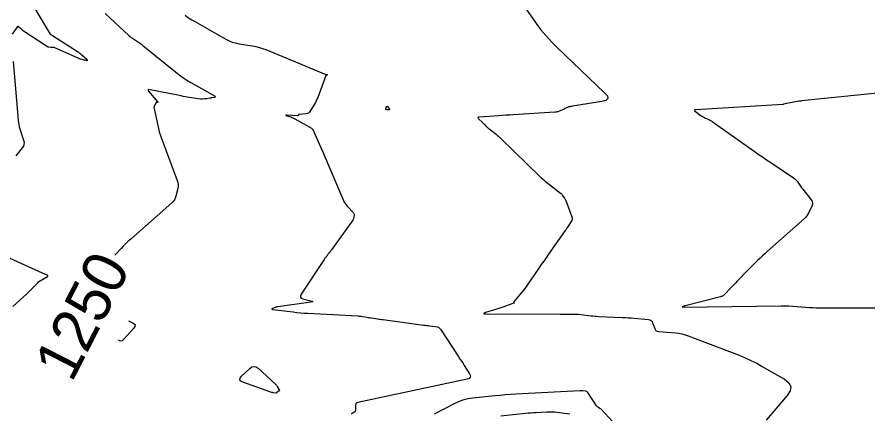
# Model space of a CAD drawing. Extents: x 658976 to 668726, y 639543 to 647196.
# Drawn here: x 662130.9 to 662247.5, y 641700.5 to 641754.9 of the extents above; entities that cross this region are included whole.
import ezdxf

# ---------------------------------------------------------------- set-up
doc = ezdxf.new("R2010")
doc.units = 0
for name, color, linetype in [('Ex_Contour Labels', 7, 'Continuous'), ('Ex_Major Contours', 7, 'Continuous'), ('Ex_Minor Contours', 7, 'Continuous')]:
    doc.layers.add(name, color=color, linetype=linetype)

msp = doc.modelspace()

# ---------------------------------------------------------------- linework, layer by layer
at = {"layer": 'Ex_Major Contours'}
for points in [[(662142.98, 641755.41), (662146.24, 641752.4), (662146.39, 641752.27), (662146.54, 641752.15), (662146.7, 641752.04), (662146.86, 641751.93), (662147.52, 641751.5), (662147.68, 641751.39), (662147.84, 641751.28), (662147.99, 641751.16), (662148.15, 641751.04), (662152.6, 641747.41), (662153.11, 641747.01), (662153.63, 641746.64), (662154.17, 641746.29), (662154.73, 641745.96), (662158.05, 641744.08), (662158.07, 641744.07), (662158.08, 641744.05), (662158.08, 641744.04), (662158.07, 641744.02), (662158.02, 641743.93), (662158, 641743.91), (662157.99, 641743.9), (662157.97, 641743.89), (662157.94, 641743.88), (662157.58, 641743.85), (662157.51, 641743.84), (662157.44, 641743.83), (662157.37, 641743.82), (662157.3, 641743.81), (662156.9, 641743.74), (662156.83, 641743.73), (662156.76, 641743.72), (662156.69, 641743.71), (662156.61, 641743.71), (662156.33, 641743.68), (662156.26, 641743.68), (662156.19, 641743.68), (662156.12, 641743.68), (662156.05, 641743.69), (662154.51, 641743.92), (662154.23, 641743.96), (662153.95, 641744.01), (662153.67, 641744.06), (662153.39, 641744.11), (662148.92, 641744.99), (662148.9, 641745), (662148.88, 641744.99), (662148.87, 641744.97), (662148.87, 641744.95), (662148.87, 641744.85), (662148.87, 641744.82), (662148.88, 641744.8), (662148.89, 641744.77), (662148.9, 641744.75), (662150.17, 641743.29), (662150.19, 641743.27), (662150.19, 641743.25), (662150.18, 641743.23), (662150.15, 641743.23), (662150.01, 641743.21), (662149.98, 641743.2), (662149.95, 641743.18), (662149.93, 641743.16), (662149.91, 641743.13), (662149.71, 641742.72), (662149.68, 641742.64), (662149.66, 641742.56), (662149.66, 641742.48), (662149.67, 641742.4), (662150.18, 641740.05), (662150.28, 641739.63), (662150.39, 641739.21), (662150.52, 641738.81), (662150.66, 641738.4), (662152.86, 641732.51), (662152.93, 641732.24), (662152.97, 641731.98), (662152.97, 641731.71), (662152.92, 641731.44), (662152.67, 641730.35), (662152.58, 641730.09), (662152.47, 641729.85), (662152.31, 641729.63), (662152.12, 641729.44), (662146.47, 641724.48), (662146.13, 641724.18), (662145.8, 641723.86), (662145.47, 641723.54), (662145.16, 641723.21), (662144.28, 641722.26)], [(662146.17, 641713.29), (662146.79, 641712.97), (662146.99, 641712.82), (662147.08, 641712.66), (662147.05, 641712.48), (662146.92, 641712.28), (662145.48, 641710.69), (662145.32, 641710.55), (662145.14, 641710.49), (662144.96, 641710.52), (662144.8, 641710.61)]]:
    msp.add_lwpolyline(points, dxfattribs=at)
msp.add_lwpolyline([(662163.08, 641706.96), (662163.37, 641707.03), (662163.66, 641706.97), (662163.94, 641706.77), (662166.29, 641704.61), (662166.37, 641704.53), (662166.44, 641704.45), (662166.5, 641704.36), (662166.56, 641704.27), (662166.83, 641703.79), (662166.85, 641703.74), (662166.85, 641703.7), (662166.83, 641703.67), (662166.79, 641703.64), (662166.53, 641703.49), (662166.52, 641703.48), (662166.51, 641703.47), (662166.49, 641703.46), (662166.48, 641703.44), (662166.45, 641703.38), (662166.44, 641703.37), (662166.43, 641703.36), (662166.41, 641703.36), (662166.4, 641703.36), (662165.99, 641703.41), (662165.91, 641703.42), (662165.84, 641703.43), (662165.77, 641703.45), (662165.7, 641703.48), (662161.84, 641704.85), (662161.55, 641705), (662161.43, 641705.19), (662161.47, 641705.41), (662161.67, 641705.66), (662162.8, 641706.75)], close=True, dxfattribs=at)
at = {"layer": 'Ex_Minor Contours'}
for points in [[(662199.55, 641757.69), (662202.07, 641754.07), (662202.72, 641753.19), (662203.41, 641752.34), (662204.15, 641751.52), (662204.92, 641750.75), (662211.45, 641744.56), (662211.82, 641744.11), (662211.88, 641743.75), (662211.63, 641743.5), (662211.07, 641743.34), (662207.02, 641742.71), (662206.9, 641742.69), (662206.79, 641742.67), (662206.67, 641742.63), (662206.56, 641742.6), (662205.89, 641742.36), (662205.89, 641742.35), (662205.88, 641742.35), (662205.88, 641742.34), (662205.88, 641742.33), (662205.89, 641742.3), (662205.89, 641742.29), (662205.89, 641742.29), (662205.89, 641742.28), (662205.88, 641742.28), (662205.13, 641741.97), (662205.09, 641741.95), (662205.05, 641741.94), (662205.01, 641741.93), (662204.96, 641741.92), (662204.79, 641741.89), (662204.74, 641741.88), (662204.7, 641741.88), (662204.65, 641741.87), (662204.61, 641741.87), (662198.91, 641741.52), (662198.42, 641741.49), (662197.92, 641741.46), (662197.42, 641741.43), (662196.93, 641741.4), (662194.25, 641741.21), (662194.13, 641741.19), (662194.08, 641741.15), (662194.09, 641741.08), (662194.16, 641740.99), (662194.66, 641740.52), (662194.73, 641740.44), (662194.81, 641740.36), (662194.89, 641740.29), (662194.97, 641740.21), (662195.27, 641739.89), (662195.35, 641739.82), (662195.43, 641739.74), (662195.51, 641739.67), (662195.6, 641739.6), (662196.56, 641738.86), (662196.74, 641738.71), (662196.93, 641738.56), (662197.1, 641738.4), (662197.28, 641738.23), (662202.52, 641733.13), (662202.8, 641732.86), (662203.1, 641732.6), (662203.4, 641732.35), (662203.7, 641732.1), (662205.4, 641730.78), (662205.48, 641730.72), (662205.56, 641730.64), (662205.62, 641730.57), (662205.68, 641730.48), (662205.92, 641730.14), (662205.97, 641730.05), (662206.02, 641729.96), (662206.07, 641729.87), (662206.11, 641729.78), (662206.95, 641727.55), (662206.99, 641727.38), (662207, 641727.21), (662206.96, 641727.05), (662206.88, 641726.89), (662206.46, 641726.27), (662206.36, 641726.12), (662206.25, 641725.96), (662206.15, 641725.81), (662206.04, 641725.66), (662203.75, 641722.4), (662203.42, 641721.93), (662203.09, 641721.46), (662202.76, 641720.99), (662202.43, 641720.51), (662200.81, 641718.16), (662200.64, 641717.91), (662200.46, 641717.67), (662200.27, 641717.43), (662200.08, 641717.2), (662198.95, 641715.84), (662198.94, 641715.83), (662198.94, 641715.82), (662198.95, 641715.81), (662198.96, 641715.8), (662199.06, 641715.75), (662199.07, 641715.75), (662199.07, 641715.75), (662199.08, 641715.75), (662199.08, 641715.74), (662199.11, 641715.74), (662199.11, 641715.74), (662199.11, 641715.74), (662199.11, 641715.74), (662199.11, 641715.74), (662197.47, 641715.15), (662197.2, 641715.06), (662196.92, 641714.96), (662196.64, 641714.87), (662196.36, 641714.78), (662195.13, 641714.4), (662194.91, 641714.32), (662194.84, 641714.26), (662194.93, 641714.23), (662195.16, 641714.21), (662205.36, 641714.2), (662205.6, 641714.2), (662205.84, 641714.2), (662206.09, 641714.2), (662206.33, 641714.2), (662207.69, 641714.19), (662207.74, 641714.19), (662207.78, 641714.19), (662207.83, 641714.19), (662207.87, 641714.18), (662209.61, 641713.97), (662209.85, 641713.94), (662210.1, 641713.92), (662210.34, 641713.9), (662210.59, 641713.88), (662213.89, 641713.73), (662214.29, 641713.71), (662214.69, 641713.69), (662215.09, 641713.66), (662215.49, 641713.62), (662217.47, 641713.44), (662217.66, 641713.4), (662217.82, 641713.31), (662217.94, 641713.18), (662218.03, 641713.01), (662218.31, 641712.22), (662218.39, 641712.05), (662218.51, 641711.92), (662218.67, 641711.84), (662218.86, 641711.8), (662221.16, 641711.61), (662221.61, 641711.56), (662222.05, 641711.48), (662222.48, 641711.36), (662222.91, 641711.22), (662229.91, 641708.54), (662230.72, 641708.21), (662231.51, 641707.85), (662232.29, 641707.45), (662233.06, 641707.03), (662236.09, 641705.26), (662236.69, 641704.79), (662236.95, 641704.26), (662236.88, 641703.68), (662236.48, 641703.03), (662233.6, 641699.63)], [(662130.28, 641752.58), (662131, 641753.66), (662131.02, 641753.67), (662131.03, 641753.68), (662131.04, 641753.68), (662131.06, 641753.67), (662131.39, 641753.36), (662131.45, 641753.31), (662131.51, 641753.25), (662131.58, 641753.2), (662131.65, 641753.16), (662135.06, 641750.9), (662135.11, 641750.87), (662135.15, 641750.85), (662135.2, 641750.84), (662135.26, 641750.83), (662135.49, 641750.82), (662135.53, 641750.81), (662135.57, 641750.81), (662135.61, 641750.81), (662135.65, 641750.81), (662135.91, 641750.79), (662135.91, 641750.79), (662135.92, 641750.79), (662135.93, 641750.79), (662135.93, 641750.79), (662139.33, 641749.29), (662139.4, 641749.27), (662139.47, 641749.24), (662139.54, 641749.22), (662139.61, 641749.2), (662139.89, 641749.13), (662140.04, 641749.09), (662140.18, 641749.06), (662140.47, 641748.99), (662140.53, 641748.98), (662140.56, 641748.99), (662140.55, 641749.01), (662140.51, 641749.05), (662139.79, 641749.72), (662139.65, 641749.84), (662139.5, 641749.96), (662139.35, 641750.07), (662139.2, 641750.17), (662135.74, 641752.38), (662135.72, 641752.4), (662135.7, 641752.41), (662135.67, 641752.43), (662135.65, 641752.44), (662135.56, 641752.49), (662135.54, 641752.51), (662135.52, 641752.53), (662135.5, 641752.55), (662135.49, 641752.57), (662133.29, 641756.23)], [(662153.94, 641755.18), (662154.4, 641754.85), (662154.87, 641754.55), (662155.35, 641754.26), (662159.53, 641751.9), (662159.95, 641751.68), (662160.39, 641751.51), (662160.84, 641751.38), (662161.3, 641751.28), (662163.18, 641750.99), (662163.65, 641750.9), (662164.11, 641750.78), (662164.56, 641750.64), (662165, 641750.47), (662173.21, 641747.08), (662173.22, 641747.08), (662173.23, 641747.08), (662173.24, 641747.07), (662173.25, 641747.07), (662173.29, 641747.07), (662173.3, 641747.07), (662173.31, 641747.07), (662173.32, 641747.07), (662173.33, 641747.07), (662173.47, 641747.03), (662173.48, 641747.03), (662173.48, 641747.02), (662173.48, 641747.02), (662173.47, 641747.01), (662173.43, 641746.97), (662173.42, 641746.96), (662173.41, 641746.95), (662173.4, 641746.95), (662173.39, 641746.96), (662173.3, 641747), (662173.29, 641747), (662173.29, 641747), (662173.28, 641747), (662173.27, 641746.99), (662173.25, 641746.97), (662173.24, 641746.96), (662173.24, 641746.95), (662173.23, 641746.95), (662173.23, 641746.94), (662172.11, 641743.91), (662172.01, 641743.67), (662171.91, 641743.44), (662171.79, 641743.22), (662171.66, 641743), (662171.05, 641741.99), (662170.95, 641741.86), (662170.83, 641741.76), (662170.69, 641741.69), (662170.53, 641741.66), (662169.55, 641741.55), (662169.52, 641741.55), (662169.5, 641741.54), (662169.48, 641741.52), (662169.47, 641741.5), (662169.41, 641741.42), (662169.4, 641741.4), (662169.38, 641741.39), (662169.36, 641741.38), (662169.34, 641741.38), (662167.88, 641741.48), (662167.76, 641741.48), (662167.72, 641741.47), (662167.76, 641741.44), (662167.86, 641741.41), (662168.44, 641741.23), (662168.58, 641741.18), (662168.72, 641741.13), (662168.85, 641741.06), (662168.99, 641740.99), (662171.28, 641739.68), (662171.3, 641739.67), (662171.31, 641739.66), (662171.33, 641739.65), (662171.34, 641739.63), (662171.39, 641739.58), (662171.41, 641739.57), (662171.42, 641739.56), (662171.43, 641739.54), (662171.44, 641739.53), (662172.68, 641736.71), (662172.89, 641736.24), (662173.09, 641735.76), (662173.3, 641735.28), (662173.5, 641734.81), (662175.66, 641729.76), (662175.76, 641729.55), (662175.88, 641729.35), (662176.01, 641729.17), (662176.16, 641729), (662176.99, 641728.13), (662177.04, 641728.05), (662177.08, 641727.98), (662177.1, 641727.89), (662177.1, 641727.81), (662177.05, 641727.44), (662177.03, 641727.35), (662177.01, 641727.26), (662176.97, 641727.18), (662176.92, 641727.1), (662173.99, 641723), (662173.95, 641722.95), (662173.91, 641722.9), (662173.87, 641722.84), (662173.83, 641722.79), (662173.66, 641722.59), (662173.62, 641722.54), (662173.58, 641722.49), (662173.54, 641722.44), (662173.5, 641722.39), (662173.22, 641722.02), (662173.16, 641721.94), (662173.1, 641721.86), (662173.04, 641721.78), (662172.99, 641721.7), (662169.84, 641716.91), (662169.74, 641716.7), (662169.74, 641716.52), (662169.86, 641716.39), (662170.08, 641716.3), (662171.18, 641716.03), (662171.39, 641715.97), (662171.46, 641715.91), (662171.38, 641715.86), (662171.17, 641715.82), (662166.63, 641715.21), (662166.53, 641715.19), (662166.44, 641715.17), (662166.35, 641715.14), (662166.26, 641715.1), (662165.91, 641714.94), (662165.84, 641714.9), (662165.82, 641714.87), (662165.85, 641714.85), (662165.92, 641714.83), (662168.73, 641714.49), (662169.23, 641714.43), (662169.73, 641714.38), (662170.24, 641714.34), (662170.74, 641714.31), (662177.6, 641713.94), (662177.75, 641713.93), (662177.91, 641713.91), (662178.07, 641713.89), (662178.23, 641713.87), (662178.86, 641713.78), (662179.01, 641713.75), (662179.17, 641713.73), (662179.33, 641713.7), (662179.48, 641713.68), (662180.31, 641713.55), (662180.5, 641713.52), (662180.69, 641713.49), (662180.88, 641713.47), (662181.07, 641713.44), (662186.62, 641712.69), (662186.82, 641712.67), (662187.03, 641712.64), (662187.24, 641712.62), (662187.45, 641712.6), (662188.28, 641712.51), (662188.48, 641712.47), (662188.65, 641712.4), (662188.8, 641712.28), (662188.93, 641712.12), (662191.48, 641708.27), (662191.66, 641707.99), (662191.85, 641707.7), (662192.03, 641707.42), (662192.21, 641707.14), (662192.92, 641705.99), (662193.04, 641705.73), (662193.02, 641705.53), (662192.88, 641705.38), (662192.62, 641705.28), (662177.59, 641702.09), (662177.47, 641702.04), (662177.38, 641701.96), (662177.32, 641701.86), (662177.3, 641701.73), (662177.3, 641701.04), (662177.28, 641700.95), (662177.25, 641700.86), (662177.2, 641700.79), (662177.13, 641700.73), (662176.8, 641700.52), (662176.71, 641700.47)], [(662130.77, 641735.9), (662131.66, 641736.99), (662131.81, 641737.22), (662131.89, 641737.46), (662131.9, 641737.72), (662131.84, 641737.99), (662131.33, 641739.55), (662131.28, 641739.7), (662131.24, 641739.84), (662131.21, 641739.99), (662131.19, 641740.15), (662131.1, 641740.75), (662131.08, 641740.9), (662131.06, 641741.06), (662131.05, 641741.21), (662131.03, 641741.36), (662130.42, 641748.84)], [(662256.08, 641745.23), (662238.44, 641743.44), (662238.33, 641743.42), (662238.07, 641743.4), (662238.06, 641743.4), (662235.99, 641742.98), (662235.98, 641742.98), (662235.97, 641742.98), (662235.96, 641742.98), (662235.95, 641742.97), (662235.91, 641742.96), (662235.9, 641742.96), (662235.89, 641742.95), (662235.88, 641742.95), (662235.87, 641742.95), (662223.97, 641742.23), (662223.81, 641742.2), (662223.75, 641742.15), (662223.77, 641742.07), (662223.9, 641741.96), (662224.69, 641741.41), (662224.81, 641741.34), (662224.94, 641741.26), (662225.06, 641741.19), (662225.19, 641741.13), (662225.71, 641740.89), (662225.83, 641740.83), (662225.96, 641740.76), (662226.08, 641740.68), (662226.2, 641740.6), (662231.95, 641736.54), (662232.51, 641736.15), (662233.07, 641735.76), (662233.64, 641735.37), (662234.21, 641734.98), (662237.35, 641732.87), (662237.48, 641732.78), (662237.6, 641732.67), (662237.71, 641732.55), (662237.82, 641732.42), (662238.2, 641731.88), (662238.3, 641731.75), (662238.4, 641731.61), (662238.5, 641731.48), (662238.6, 641731.35), (662239.76, 641729.86), (662239.88, 641729.66), (662239.93, 641729.45), (662239.93, 641729.24), (662239.85, 641729.02), (662239.43, 641728.11), (662239.32, 641727.89), (662239.18, 641727.69), (662239.03, 641727.5), (662238.85, 641727.32), (662233.74, 641722.78), (662233.41, 641722.47), (662233.07, 641722.17), (662232.75, 641721.86), (662232.42, 641721.54), (662230.82, 641719.96), (662230.66, 641719.8), (662230.5, 641719.64), (662230.35, 641719.47), (662230.19, 641719.31), (662229.57, 641718.65), (662229.42, 641718.48), (662229.26, 641718.32), (662229.1, 641718.15), (662228.94, 641717.99), (662227.7, 641716.72), (662227.67, 641716.69), (662227.65, 641716.68), (662227.62, 641716.66), (662227.59, 641716.65), (662227.45, 641716.62), (662227.39, 641716.6), (662227.32, 641716.58), (662222.48, 641715.35), (662222.43, 641715.33), (662222.39, 641715.32), (662222.35, 641715.3), (662222.3, 641715.28), (662222.13, 641715.2), (662222.1, 641715.19), (662222.09, 641715.17), (662222.1, 641715.17), (662222.14, 641715.16), (662235.63, 641715.33), (662235.73, 641715.33), (662235.83, 641715.33), (662235.93, 641715.33), (662236.03, 641715.33), (662236.57, 641715.34), (662236.6, 641715.34), (662236.64, 641715.34), (662236.67, 641715.34), (662236.7, 641715.33), (662239.53, 641715.12), (662239.97, 641715.09), (662240.41, 641715.07), (662240.85, 641715.06), (662241.28, 641715.05), (662248.93, 641715.04)], [(662130.3, 641715.25), (662132.19, 641716.94), (662132.37, 641717.11), (662132.56, 641717.28), (662132.74, 641717.46), (662132.91, 641717.64), (662133.72, 641718.47), (662133.85, 641718.6), (662133.98, 641718.71), (662134.13, 641718.82), (662134.28, 641718.91), (662135.05, 641719.36), (662135.11, 641719.4), (662135.13, 641719.45), (662135.1, 641719.49), (662135.04, 641719.53), (662134.37, 641719.83), (662128.48, 641722.48)], [(662214.18, 641697.69), (662210.95, 641701.14), (662210.9, 641701.18), (662210.85, 641701.22), (662210.8, 641701.26), (662210.75, 641701.3), (662210.53, 641701.42), (662210.48, 641701.46), (662210.43, 641701.5), (662210.39, 641701.54), (662210.35, 641701.59), (662209.16, 641703.42), (662209.1, 641703.49), (662209.03, 641703.55), (662208.94, 641703.59), (662208.85, 641703.61), (662208.44, 641703.67), (662208.34, 641703.68), (662208.24, 641703.68), (662208.13, 641703.68), (662208.03, 641703.68), (662199.27, 641703.2), (662198.55, 641703.16), (662197.83, 641703.11), (662197.11, 641703.05), (662196.4, 641702.98), (662193.4, 641702.67), (662192.76, 641702.58), (662192.13, 641702.42), (662191.52, 641702.2), (662190.92, 641701.93), (662188.09, 641700.45)], [(662206.69, 641700.48), (662204.91, 641700.7), (662204.57, 641700.74), (662204.22, 641700.76), (662203.88, 641700.76), (662203.54, 641700.75), (662202.04, 641700.67), (662201.68, 641700.65), (662201.32, 641700.62), (662200.96, 641700.59), (662200.59, 641700.56), (662197.22, 641700.21)]]:
    msp.add_lwpolyline(points, dxfattribs=at)
msp.add_lwpolyline([(662181.72, 641742.21), (662181.7, 641742.21), (662181.68, 641742.21), (662181.67, 641742.21), (662181.6, 641742.21), (662181.58, 641742.22), (662181.57, 641742.22), (662181.55, 641742.23), (662181.54, 641742.24), (662181.45, 641742.31), (662181.43, 641742.33), (662181.42, 641742.35), (662181.42, 641742.37), (662181.43, 641742.39), (662181.56, 641742.65), (662181.58, 641742.69), (662181.61, 641742.7), (662181.64, 641742.69), (662181.67, 641742.66), (662181.93, 641742.29), (662181.95, 641742.27), (662181.95, 641742.25), (662181.93, 641742.24), (662181.9, 641742.23), (662181.73, 641742.21)], close=True, dxfattribs=at)

# ---------------------------------------------------------------- texts
at = {"layer": 'Ex_Contour Labels'}
msp.add_text('1250', height=6, rotation=62.889, dxfattribs=at).set_placement((662138.39, 641704.68))

doc.saveas('drawing.dxf')
